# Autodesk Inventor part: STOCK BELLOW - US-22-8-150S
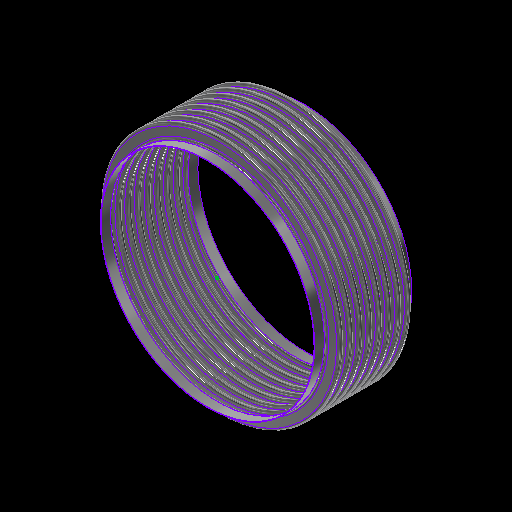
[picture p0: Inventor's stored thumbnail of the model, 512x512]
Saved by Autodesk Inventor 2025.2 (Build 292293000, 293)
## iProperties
Category: 16 GA (0.060 THICK)
RuleStatus: InUse
Created: 2024-01
Part Number: STOCK BELLOW - US-22-8-150S
Project: =STOCK BELLOWS: <Stock Number><SFILL>
Material: ASTM A240-304
Description: =STOCK BELLOWS: <Stock Number>, <SID_> I.D., <SOD_> O.D., <SPLY_> PLY, <Category>, <SNET_CONS> CONS.<PITCH_><STANGENT_> TANGENT<SFILL>
Document SubType Name: Sheet Metal
Designer: GS
Stock Number: U.S-22-8-150S
Surface Area: 26212.6 cm^2
Volume: 1985.13 cm^3
Sheet Metal Rule: Default
Appearance: STAINLESS STEEL
Mass: 15994.8 g
Density: 8.05729 g/cm^3
THK: 0.036
ID: 3.500
OD: 4.250
CONS_: 2
PITCH: 0.500
TANGENT: 0.500
BELLOWS_UPSET: 0.000
d79: 1.000
d82: 1.000
d83: 26.000
d84: 24.000
d174: 8
d214: 8
STHK_: 0.060
SID_: 22.000
SOD_: 24.750
SPITCH_: 1.000
STANGENT__: 1.000
SBELLOWS_UPSET_: 0.000
SDIFF_TAN: 1.000
d252: 2
d275: 2
d287: 0.050
d289: 0.500
d290: 0.000
SOD_NECK: 22 1/8
PLY: 1
PSET: 4.178
PBAR: 1.035
COUNTER: 1.500
NET_TUBE: 3.071
CONS: 2
S_CONS: 0
NET_CONS: 2
ID_M: 88.90 mm
OD_M: 107.95 mm
THK_M: 0.91 mm
ID_U: 3.500 in
OD_U: 4.250 in
THK_U: 0.036 in
TANGENT2: 0.500
TAN_TO_TAN: 1.000 in
d80: 2.571
d81: 10
SID: 2.375
SCONS_: 8
SPITCH: 0.250
STANGENT_: 1.000
SBELLOWS_UPSET: 0.000
SNET_CONS: 8
SS_CONS: 0
SCONS: 8
d190: 8
d191: 1
d192: 1
d193: 8
d194: 0
SIZE: 22.00
PRESSURE: 150
d230: 8
STANGENT: 4.000
SPLY_: 1
d233: 8
d234: 0
d263: 2
d265: 1
d268: 2
d269: 0
d286: 2
d288: 1
d291: 2
d292: 0
SREROLL: 0.750
BLETP: 0.000 ul
PRES_Copy: 85
MATTABLE: 20 GA (0.036 THICK)
PART_NUMBER: U.S-22-8-150S
PITCH_: =, <SPITCH_> PITCH,
CFILL: .
SFILL: .
MESH: ,
COMP: 1.49
EXT: 0.75
LAT: 0.17
ANG: 458
ASR: 4132
LSR: 52913
ANSR: 7578
PRES: 150
COMPM: 14.9
EXTM: 7.45
LATM: 1.70
ASRM: 723.637
PRESM: 10.342
LSRM: 9266.654
ANSRM: 1327.135
TEMPMIN: 20
TEMPMAX: 800
TEMPMINM: -7
TEMPMAXM: 427
WEIGHTM: 15.995
WEIGHT: 35.262
Author: GS
Keywords: 20 GA (0.036 THICK)
Comments: =STOCK BELLOW - <STOCK NUMBER>
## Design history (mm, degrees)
sketch "Sketch2"
  geometry: L1 (0, -177.245)-(0, 562.856) reference; L2 (45.364, 0)-(44.45, 0); L3 (48.082, -2.718)-(50.343, -2.718); L4 (48.082, -3.632)-(50.343, -3.632); L5 (50.343, -9.982)-(48.082, -9.982); L6 (50.343, -9.068)-(48.082, -9.068); L7 (45.364, -12.7)-(44.45, -12.7); L8 (48.082, 0)-(48.082, -12.7); L9 (50.343, -6.35)-(53.975, -6.35); L10 (44.45, 0)-(44.45, -12.7); L11 (20.376, 102.841)-(20.376, 101.926); L12 (58.262, 457.127)-(58.262, 349.177); L13 (58.262, 444.427)-(58.262, 336.477); L14 (93.133, -58.817)-(93.133, -71.517); L15 (118.746, -66.401)-(118.746, -66.401); L16 (50.343, -9.068)-(50.343, -9.982); L17 (48.082, -9.068)-(48.082, -9.982); L18 (48.082, -9.525)-(50.343, -9.525); L19 (53.975, 0)-(53.975, -12.7); L20 (-50.343, -9.068)-(-50.343, -9.982); L21 (-50.343, -2.718)-(-48.082, -2.718); L22 (-50.343, -3.632)-(-48.082, -3.632); L23 (-48.082, -9.068)-(-50.343, -9.068); L24 (-50.343, -9.525)-(-48.082, -9.525); L25 (-48.082, -9.982)-(-50.343, -9.982); L26 (-48.082, -9.068)-(-48.082, -9.982); L27 (-44.45, 0.653)-(-44.45, -12.047); L28 (-48.082, -6.35)-(-44.45, -6.35); L29 (-50.343, 0.653)-(-50.343, -12.7); L30 (-53.061, 0)-(-53.975, 0); L31 (-53.975, 0)-(-53.975, -12.7); L32 (-53.061, -12.7)-(-53.975, -12.7); A1 r 2.718 centre (48.082, 0) between (45.364, 0) and (48.082, -2.718); A2 r 3.632 centre (48.082, 0) between (44.45, 0) and (48.082, -3.632); A3 r 3.632 centre (50.343, -6.35) between (50.343, -9.982) and (50.343, -2.718); A4 r 2.718 centre (50.343, -6.35) between (50.343, -9.068) and (50.343, -3.632); A5 r 2.718 centre (48.082, -12.7) between (48.082, -9.982) and (45.364, -12.7); A6 r 3.632 centre (48.082, -12.7) between (48.082, -9.068) and (44.45, -12.7); A7 r 3.175 centre (50.343, -6.35) between (50.343, -9.525) and (53.518, -6.35); A8 r 3.175 centre (48.082, -12.7) between (48.082, -9.525) and (44.907, -12.7); A9 r 2.718 centre (-50.343, -12.7) between (-50.343, -9.982) and (-53.061, -12.7); A10 r 2.718 centre (-48.082, -6.35) between (-48.082, -9.068) and (-48.082, -3.632); A11 r 3.175 centre (-48.082, -6.35) between (-48.082, -9.525) and (-44.907, -6.35); A12 r 3.632 centre (-48.082, -6.35) between (-48.082, -9.982) and (-48.082, -2.718); A13 r 3.175 centre (-50.343, -12.7) between (-50.343, -9.525) and (-53.518, -12.7); A14 r 3.632 centre (-50.343, -12.7) between (-50.343, -9.068) and (-53.975, -12.7); A15 r 2.718 centre (-50.343, 0) between (-53.061, 0) and (-50.343, -2.718); A16 r 3.632 centre (-50.343, 0) between (-53.975, 0) and (-50.343, -3.632); 10 further points
  constraints: 62 end point, 38 point on circle, 20 tangent, 16 centre point, 12 parallel, 9 midpoint, 7 vertical, 6 coincident, 6 concentric, 6 point on line, 4 equal radius, 4 perpendicular, 3 horizontal, 1 collinear, 1 horizontal alignment, 10 other
  dimensions: "THK" = 0.9144 distance of L11.start L11.end; "ID" = 88.9 distance of L11.end point (20.376, 13.026); "OD" = 107.95 distance of L12.start L12.end; "PITCH" = 12.7 distance of L12.start L13.start; "TANGENT" = 12.7 distance of L14.start L14.end; "BELLOWS_UPSET" = 0 distance of L15.start L15.end; "d43" = 88.9 diameter of L10 L1 (= ID); "d44" = 107.95 diameter of L9.end L1 (= OD); "d45" = 0.9144 distance between parallel lines of L5 L6 (computed from THK, PLY); "d46" = 3.6322 radius of A3 (computed from PITCH, THK, PLY); "UPSET_PITCH" = 12.7 distance of L2.end L7.end (derived); "SIDEWALL_ANGLE" = 360 deg dimension on L3 L9 (derived); "CON_GAP" = 5.4356 distance of point (48.082, -9.068) point (48.082, -3.632) (derived); "TAN1" = 4.98728 dimension on A8 (derived); "TAN2" = 4.98728 dimension on A7 (derived); "LEG1" = 2.2606 distance of L18.start L18.end (derived); "d278" = 0.9144 distance between parallel lines of L25 L23 (derived); "d279" = 3.6322 radius of A12 (derived); "d280" = 12.7 distance of L30.end L31.end (derived); "d281" = 360 deg dimension on L21 L28 (derived); "d282" = 5.4356 distance of point (-50.343, -9.068) point (-50.343, -3.632) (derived); "d283" = 4.98728 dimension on A13 (derived); "d284" = 4.98728 dimension on A11 (derived); "d285" = 2.2606 distance of L24.start L24.end (derived); "d293" = 88.9 diameter of L27 L1 (derived); "d294" = 107.95 diameter of L31 L1 (derived)
  node "Sketch Rectangular Pattern1" dims "d31" = 25.4, "ID" = 88.9
  node "Sketch Rectangular Pattern2" dims "d39" = 25.4, "PITCH" = 12.7
revolve "CONS" stored, may be unused: angle "d48" = 90 deg
node "BELLOW MIDPLANE"
pattern_linear "Rectangular Pattern2" dims "d52" = 12.7 (= UPSET_PITCH)
sketch "Sketch5"
  geometry: C1 r 45.364 at (0, 0) reference; C2 r 44.45 at (0, 0) reference
extrude "TANGENT" new body sketch "Sketch5" distance "d53" = 12.7 (= TANGENT); taper "d54" = 0 deg
revolve "SAMETAN" stored, may be unused: angle "d65" = 90 deg
revolve "DIFFTAN" stored, may be unused: angle "d70" = 90 deg
sketch "Sketch9"
  geometry: L1 (53.319, 0)-(-53.319, 0) reference; L2 (0, -17.78)-(0, 17.78) reference; L3 (38.085, 0)-(-38.085, 0); L4 (38.085, -11.906)-(38.085, 11.906); L5 (25.385, -11.906)-(25.385, 11.906); L6 (13.15, 11.906)-(13.15, -11.906); L7 (-25.385, -11.906)-(-25.385, 11.906); L8 (-38.085, -11.906)-(-38.085, 11.906); L9 (37.291, -11.906)-(37.291, 11.906); L10 (38.085, -11.906)-(37.291, -11.906); L11 (38.085, 11.906)-(37.291, 11.906); L12 (13.546, 11.906)-(12.753, 11.906); L13 (12.753, 11.906)-(12.753, -11.906); L14 (12.753, -11.906)-(13.546, -11.906); L15 (13.546, -11.906)-(13.546, 11.906); L16 (-13.546, 11.906)-(-13.546, -11.906); L17 (-13.15, 11.906)-(-13.15, -11.906); L18 (-13.546, -11.906)-(-12.753, -11.906); L19 (-12.753, -11.906)-(-12.753, 11.906); L20 (-12.753, 11.906)-(-13.546, 11.906); L21 (-38.085, -11.906)-(-37.291, -11.906); L22 (-37.291, -11.906)-(-37.291, 11.906); L23 (-37.291, 11.906)-(-38.085, 11.906); L24 (-38.085, 11.906)-(-38.085, -11.906); L25 (38.085, -0.397)-(-38.085, -0.397); L26 (-38.085, -0.397)-(-38.085, 0.397); L27 (-38.085, 0.397)-(38.085, 0.397); L28 (38.085, 0.397)-(38.085, -0.397); L29 (-38.085, 11.906)-(38.085, 11.906); L30 (38.085, 11.906)-(38.085, 12.7); L31 (38.085, 12.7)-(-38.085, 12.7); L32 (-38.085, 12.7)-(-38.085, 11.906); L33 (38.085, -11.906)-(-38.085, -11.906); L34 (-38.085, -11.906)-(-38.085, -12.7); L35 (-38.085, -12.7)-(38.085, -12.7); L36 (38.085, -12.7)-(38.085, -11.906); 30 further points
  constraints: 68 end point, 13 midpoint, 13 parallel, 8 horizontal, 7 perpendicular, 6 equal length, 3 point on line, 2 vertical, 14 other
  dimensions: "d115" = 23.8125 distance of L4.start L4.end (derived); "d116" = 12.7 distance between parallel lines of L4 L5 (derived); "d117" = 12.23516 distance between parallel lines of L5 L6 (derived); "d125" = 38.53427 distance between parallel lines of L7 L6 (derived); "d127" = 12.7 distance between parallel lines of L8 L7 (derived); "d128" = 24.93516 distance between parallel lines of L6 L4 (derived); "d130" = 76.16943 distance between parallel lines of L8 L4 (derived); "RULER_THK" = 0.79375 distance between parallel lines of L4 L9; "d135" = 0.79375 distance of L13.end L14.end (derived); "d138" = 26.29911 distance of L13.end L16.end (derived); "d143" = 0.79375 distance of L22.end L8.end (derived); "d144" = 0.79375 distance between parallel lines of L27 L25 (derived)
extrude "RULER" join sketch "Sketch9" distance "d149" = 0.79375 (derived); taper "d150" = 0 deg
extrude "BARS" join sketch "Sketch9" distance "d151" = 0.79375 (derived); taper "d152" = 0 deg
pattern_linear "Rectangular Pattern4" dims "d155" = 26.29911 (derived)
sketch "Sketch13"
  geometry: L1 (93.149, -52.467)-(93.149, -77.867); L2 (280.924, 0)-(279.4, 0); L3 (280.924, -25.4)-(279.4, -25.4); L4 (307.213, -19.812)-(286.512, -19.812); L5 (307.213, -18.288)-(286.512, -18.288); L6 (307.213, -12.7)-(314.325, -12.7); L7 (286.512, -5.588)-(307.213, -5.588); L8 (286.512, 0)-(286.512, -25.4); L9 (279.4, 0)-(279.4, -25.4); L10 (58.254, 132.219)-(58.254, -496.431); L11 (58.254, 106.819)-(58.254, -521.831); L12 (58.254, 56.019)-(58.254, -572.631); L13 (58.254, 30.619)-(58.254, -598.031); L14 (58.254, 5.219)-(58.254, -623.431); L15 (58.254, -20.181)-(58.254, -648.831); L16 (58.254, -45.581)-(58.254, -674.231); L17 (58.254, 81.419)-(58.254, -547.231); L18 (20.376, 103.45)-(20.376, 101.926); L19 (286.512, -7.112)-(307.213, -7.112); L20 (0, -835.521)-(0, 293.509) reference; L21 (-62.865, 0)-(377.19, 0) reference; A1 r 5.588 centre (286.512, 0) between (280.924, 0) and (286.512, -5.588); A2 r 5.588 centre (286.512, -25.4) between (286.512, -19.812) and (280.924, -25.4); A3 r 7.112 centre (286.512, -25.4) between (286.512, -18.288) and (279.4, -25.4); A4 r 5.588 centre (307.213, -12.7) between (307.213, -18.288) and (307.213, -7.112); A5 r 7.112 centre (307.213, -12.7) between (307.213, -19.812) and (307.213, -5.588); A6 r 7.112 centre (286.512, 0) between (279.4, 0) and (286.512, -7.112); 6 further points; 1 other entity
  constraints: 38 end point, 15 point on circle, 9 tangent, 6 centre point, 6 parallel, 5 vertical alignment, 4 point on line, 4 vertical, 3 coincident, 3 concentric, 2 collinear, 2 equal radius, 1 horizontal, 1 perpendicular, 23 other
  dimensions: "SBELLOWS_UPSET_" = 0 distance of point (118.762, -66.401) point (118.762, -66.401); "STOTAL_THK_BELLOW__" = 1.524 distance between parallel lines of L4 L5 (derived); "d224" = 7.112 radius of A5 (derived); "d225" = 25.4 distance of L2.end L3.end (derived); "SSIDEWALL_ANGLE_" = 0 deg angle of L7 L6 (derived); "SSCON_GAP_" = 11.176 distance of point (286.512, -18.288) point (286.512, -7.112) (derived); "d235" = 558.8 diameter of L9 L20 (derived); "d236" = 628.65 diameter of L6.end L20 (derived)
  node "Sketch Rectangular Pattern4" dims "d228" = 25.4
  node "Sketch Rectangular Pattern5" dims "d229" = 25.4
revolve "SBELLOW" stored, may be unused: angle "d197" = 90 deg
pattern_linear "Rectangular Pattern5" dims "d204" = 25.4 (derived)
revolve "STANGENT" stored, may be unused: angle "d240" = 90 deg
revolve "SSAMETAN" stored, may be unused: angle "d241" = 90 deg
revolve "SDIFFTAN" stored, may be unused: angle "d246" = 90 deg
revolve "INVCON" stored, may be unused: angle "d295" = 90 deg
pattern_linear "Rectangular Pattern6" dims "d298" = 12.7 (derived)
revolve "INVTANGENT" stored, may be unused: angle "d302" = 90 deg
revolve "INVSAMETAN" stored, may be unused: angle "d307" = 90 deg
revolve "INVDIFFTAN" stored, may be unused: angle "d312" = 90 deg
sketch "ID BELLOW MOUNT CALC"
  geometry: L1 (44.45, 0)-(38.1, 0); L2 (38.1, 0)-(38.1, 12.7); L3 (38.1, 12.7)-(44.45, 12.7); L4 (44.45, 12.7)-(44.45, 0); L5 (36.513, 12.7)-(35.598, 12.7); L6 (35.598, 12.7)-(35.598, 0); L7 (35.598, 0)-(36.513, 0); L8 (36.513, 0)-(36.513, 12.7); L9 (0, -2.54)-(0, 15.24) reference; L10 (-8.89, 0)-(53.34, 0) reference; 1 further point
  constraints: 16 end point, 5 parallel, 2 collinear, 2 horizontal, 2 perpendicular
  dimensions: "d314" = 12.7 distance of L5.end L6.end (derived); "d315" = 0.9144 distance of L5.start L5.end (derived); "IG" = 1.5875 distance between parallel lines of L2 L8; "PIPE_OD" = 88.9 diameter of L4 L9; "PIPE_WALL" = 6.35 distance of L2.end L3.end; "ID_MT_BELLOW" = 71.1962 diameter of L6 L9 (derived)
revolve "CFILL" stored, may be unused: angle "d320" = 90 deg
pattern_linear "Rectangular Pattern7" dims "d323" = 12.7 (derived)
revolve "SFILL" stored, may be unused: angle "d324" = 90 deg
pattern_linear "Rectangular Pattern8" dims "d327" = 25.4 (derived)
node "STOCK BELLOW MIDPLANE"
node "BELLOW"
sketch "Sketch6"
  geometry: L1 (-12.7, 45.364)-(0, 45.364); L2 (0, 45.364)-(0, 44.45); L3 (0, 44.45)-(-12.7, 44.45); L4 (-12.7, 44.45)-(-12.7, 45.364); L5 (10.16, 0)-(-60.96, 0) reference; L6 (-38.1, -89.422)-(-38.1, 153.44) reference; 1 further point
  constraints: 8 end point, 2 parallel, 1 horizontal, 1 perpendicular
  dimensions: "d61" = 12.7 distance of L2.end L3.end (derived); "d62" = 0.9144 distance of L1.end L2.end (derived); "d63" = 88.9 diameter of L3 L5 (derived); "d64" = 25.4 distance between parallel lines of L4 L6 (derived)
sketch "Sketch12"
  geometry: 1 further point
sketch "Sketch14"
  geometry: L1 (-25.4, 280.924)-(0, 280.924); L2 (0, 280.924)-(0, 279.4); L3 (0, 279.4)-(-25.4, 279.4); L4 (-25.4, 279.4)-(-25.4, 280.924); L5 (5.08, 0)-(-30.48, 0) reference; L6 (0, -56.185)-(0, 337.109) reference; 1 further point
  constraints: 8 end point, 2 parallel, 1 collinear, 1 horizontal, 1 perpendicular
  dimensions: "d237" = 1.524 distance of L3.end L1.start (derived); "d238" = 558.8 diameter of L3 L5 (derived); "d239" = 25.4 distance of L1.start L1.end (derived); "SOD_NECK" = 561.848 diameter of L1 L5 (derived)
sketch "Sketch15"
  geometry: L1 (-56.185, 0)-(337.109, 0) reference; L2 (279.4, -203.2)-(280.924, -203.2); L3 (280.924, -203.2)-(280.924, -228.6); L4 (280.924, -228.6)-(279.4, -228.6); L5 (279.4, -228.6)-(279.4, -203.2); L6 (0, -276.86)-(0, 60.96) reference; 1 further point
  constraints: 8 end point, 2 parallel, 1 horizontal, 1 perpendicular
  dimensions: "d205" = 25.4 distance of L4.end L2.start (derived); "d206" = 1.524 distance of L3.end L4.end (derived); "d207" = 558.8 diameter of L5 L6 (derived); "d208" = 203.2 distance between parallel lines of L1 L2 (derived)
node "TANGENT_"
node "SAME_TAN"
sketch "Sketch8"
  geometry: L1 (45.364, -25.4)-(44.45, -25.4); L2 (44.45, -25.4)-(44.45, -38.1); L3 (44.45, -38.1)-(45.364, -38.1); L4 (45.364, -38.1)-(45.364, -25.4); L5 (0, -48.26)-(0, 22.86) reference; L6 (-89.422, 0)-(153.44, 0) reference; 1 further point
  constraints: 8 end point, 2 parallel, 1 horizontal, 1 perpendicular
  dimensions: "d66" = 88.9 diameter of L2 L5 (derived); "TOTAL_THK_BELLOW" = 0.9144 distance of L2.end L3.end (derived); "d68" = 25.4 distance between parallel lines of L1 L6 (derived); "d69" = 12.7 distance of L1.end L2.end (derived)
node "DIFF_TAN"
node "Sketch Rectangular Pattern3" dims "d138" = 26.29911 (derived), "d141" = 25.4
node "SBELLOW_"
node "STANGENT_"
node "SSAME_TAN"
sketch "Sketch16"
  geometry: L1 (280.924, -203.2)-(279.4, -203.2); L2 (279.4, -203.2)-(279.4, -228.6); L3 (279.4, -228.6)-(280.924, -228.6); L4 (280.924, -228.6)-(280.924, -203.2); L5 (0, -276.86)-(0, 60.96) reference; L6 (-56.185, 0)-(337.109, 0) reference; 1 further point
  constraints: 8 end point, 2 parallel, 1 horizontal, 1 perpendicular
  dimensions: "SDIFF_TAN" = 25.4 distance of L3.end L1.start; "d243" = 1.524 distance of L2.end L3.end (derived); "d244" = 203.2 distance between parallel lines of L1 L6 (derived); "d245" = 558.8 diameter of L2 L5 (derived)
node "SDIFF_TAN"
body "Solid15"
sketch "Sketch17"
  geometry: L1 (53.975, 12.7)-(53.061, 12.7); L2 (53.061, 12.7)-(53.061, 0); L3 (53.061, 0)-(53.975, 0); L4 (53.975, 0)-(53.975, 12.7); L5 (0, -2.54)-(0, 15.24) reference; L6 (-10.795, 0)-(64.77, 0) reference; 2 further points
  constraints: 8 end point, 2 parallel, 1 horizontal, 1 midpoint, 1 perpendicular, 1 point on line
  dimensions: "INVTANGENT" = 12.7 distance of L3.end L1.start (derived); "d300" = 0.9144 distance of L1.start L1.end (derived); "d301" = 107.95 diameter of L4 L5 (derived)
body "Solid16"
sketch "Sketch18"
  geometry: L1 (53.975, -25.4)-(53.061, -25.4); L2 (53.061, -25.4)-(53.061, -38.1); L3 (53.061, -38.1)-(53.975, -38.1); L4 (53.975, -38.1)-(53.975, -25.4); L5 (-10.795, 0)-(64.77, 0) reference; L6 (0, -48.26)-(0, 22.86) reference; 1 further point
  constraints: 8 end point, 2 parallel, 1 horizontal, 1 perpendicular
  dimensions: "d303" = 25.4 distance between parallel lines of L1 L5 (derived); "d304" = 12.7 distance of L3.end L1.start (derived); "d305" = 0.9144 distance of L2.end L3.end (derived); "d306" = 107.95 diameter of L4 L6 (derived)
body "Solid17"
sketch "Sketch19"
  geometry: L1 (53.975, -25.4)-(53.061, -25.4); L2 (53.061, -25.4)-(53.061, -38.1); L3 (53.061, -38.1)-(53.975, -38.1); L4 (53.975, -38.1)-(53.975, -25.4); L5 (0, -48.26)-(0, 22.86) reference; L6 (-10.795, 0)-(64.77, 0) reference; 1 further point
  constraints: 8 end point, 2 parallel, 1 horizontal, 1 perpendicular
  dimensions: "d308" = 12.7 distance of L1.end L2.end (derived); "d309" = 107.95 diameter of L4 L5 (derived); "d310" = 0.9144 distance of L2.end L3.end (derived); "d311" = 25.4 distance between parallel lines of L1 L6 (derived)
body "Solid18"
body "Solid19"
body "Solid20"
other parameters: "BMPL" = -101.6, "PSET" = 106.1212 (computed from OD, THK, PLY) [user parameter], "PBAR" = 26.29911 (= 0.570796 x PITCH + OD - ID) [user parameter; used in 1 equation term], "COUNTER" = 15 [user parameter], "NET_TUBE" = 77.99823 (computed from CONS_, PBAR, TANGENT) [user parameter], "S_CONS" = 0 [user parameter; used in 1 equation term], "ID_M" = 88.9 (= ID) [user parameter], "OD_M" = 107.95 (= OD) [user parameter], "THK_M" = 0.9144 (= THK) [user parameter], "ID_U" = 88.9 (= ID) [user parameter], "OD_U" = 107.95 (= OD) [user parameter], "THK_U" = 0.9144 (= THK) [user parameter], "D_UNITS" = 0 [user parameter], "TANGENT2" = 12.7 [user parameter], "TAN_TO_TAN" = 25.4 [user parameter], "OD_NECK" = 90.7288 [user parameter], "d79" = 25.4, "d80" = 65.29823 [user parameter], "d82" = 25.4, "d83" = 660.4, "d84" = 609.6, "sa_0" = 4, "FRAME_THK" = 0.79375 [user parameter], "CON_FLAT" = 12.23516 [user parameter], "SID" = 60.325 [user parameter], "SPITCH" = 6.35 [user parameter], "STANGENT_" = 25.4 [user parameter], "SBELLOWS_UPSET" = 0 [user parameter], "SS_CONS" = 0 [user parameter], "STAN_TO_TAN_" = 203.2 [user parameter], "d100" = 1.524 [user parameter], "d191" = 25.4 [user parameter], "d194" = 0 [user parameter], "STANGENT" = 101.6 [user parameter], "d234" = 0 [user parameter], "SUPSET_PITCH_" = 25.4 [user parameter], "d269" = 0 [user parameter], "d287" = 1.27, "d289" = 12.7, "d290" = 0, "d292" = 0 [user parameter], "Thickness" = 3.048 (derived), "KFactor" = 4.4, "BendRadius" = 3.048 (derived), "BendReliefWidth" = 3.048 (derived), "BendReliefDepth" = 1.524 (derived), "CornerReliefSize" = 12.192 (derived), "SeamGap" = 0.00508, "MinimumRemnant" = 6.096 (derived), "TransitionRadius" = 3.048 (derived), "JacobiRadiusSize" = 3.048 (derived), "GapSize" = 3.048 (derived), "SREROLL" = 19.05 [user parameter], "CUR_STK_PITCH" = 25.4 [user parameter], "d328" = -101.6 (derived), "ASR" = 41320 [user parameter], "LSR" = 529130 [user parameter], "ANSR" = 75780 [user parameter], "BLETP" = 0 [user parameter], "ASRM" = 7236.3716 [user parameter], "PRESM" = 103.41975 [user parameter], "LSRM" = 92666.5369 [user parameter], "ANSRM" = 13271.3514 [user parameter], "TEMPMIN" = 2664.83333 [user parameter], "TEMPMAX" = 6998.16667 [user parameter], "TEMPMINM" = 2664.83333 [user parameter], "TEMPMAXM" = 6998.16667 [user parameter], "WEIGHT" = 159.94785 [user parameter], "WEIGHTM" = 0.15995 [user parameter]
